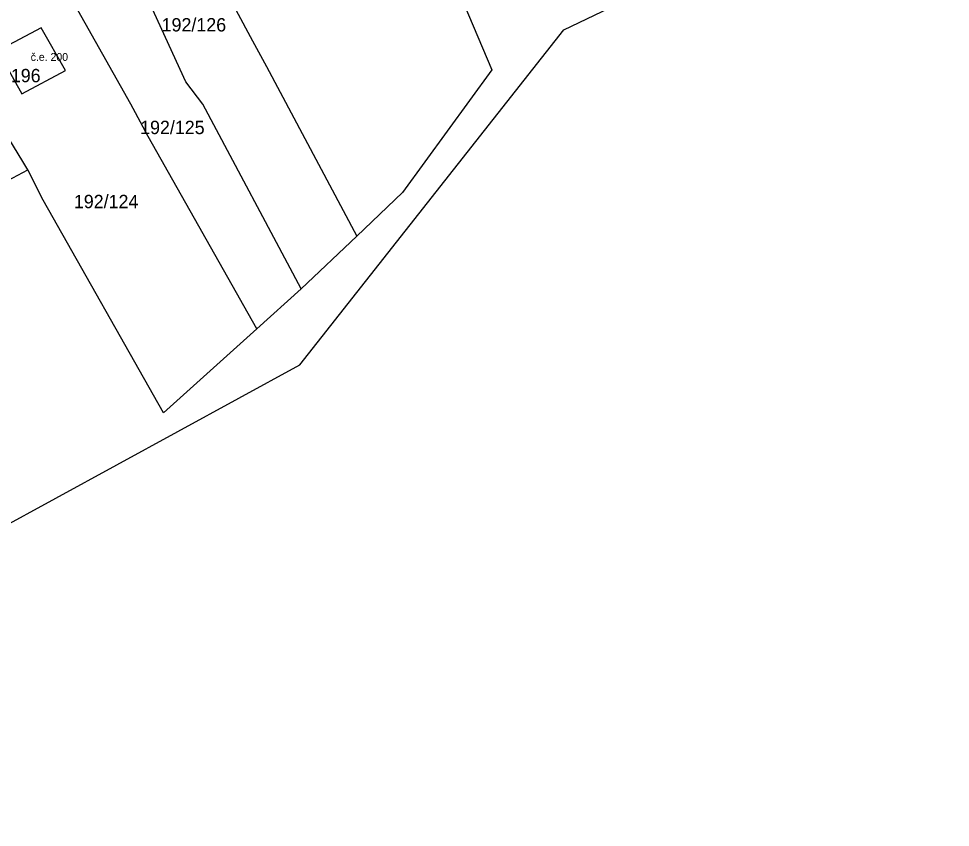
# Model space of a CAD drawing. Extents: x -887272 to -877616, y -1026687 to -1019819.
# Drawn here: x -882201.9 to -882083.2, y -1024320.7 to -1024217.6 of the extents above; entities that cross this region are included whole.
import ezdxf

# ---------------------------------------------------------------- set-up
doc = ezdxf.new("R2010")
doc.units = 0
for name, color, linetype in [('Definiční body', 7, 'Continuous'), ('Hranice parcel', 7, 'Continuous'), ('Parcelní čísla', 7, 'Continuous'), ('Polygon budovy', 7, 'Continuous')]:
    doc.layers.add(name, color=color, linetype=linetype)

msp = doc.modelspace()

# ---------------------------------------------------------------- linework, layer by layer
at = {"layer": 'Hranice parcel'}
for p, q in [((-882180.56, -1024225.66), (-882185.83, -1024214.12)), ((-882214.06, -1024243.9), (-882200.68, -1024236.89)), ((-882158.78, -1024245.34), (-882165.85, -1024252.03)), ((-882165.85, -1024252.03), (-882171.52, -1024257.13))]:
    msp.add_line(p, q, dxfattribs=at)
for points in [[(-882425.59, -1024292.38), (-882421.44, -1024309.52), (-882387.34, -1024318.62), (-882335.2, -1024317.62), (-882324.6, -1024318.36), (-882301.38, -1024320.66), (-882228.26, -1024295.72), (-882166.04, -1024261.72), (-882132.4, -1024219.02), (-882083.16, -1024195.4)], [(-882183.3, -1024199.45), (-882172.08, -1024220.45), (-882170.3, -1024223.69), (-882158.78, -1024245.34)], [(-882171.52, -1024257.13), (-882185.35, -1024232.63), (-882186.97, -1024229.61), (-882187.58, -1024228.52), (-882201.44, -1024203.82)], [(-882145.75, -1024214.26), (-882141.56, -1024224.13), (-882152.95, -1024239.76), (-882158.78, -1024245.34)], [(-882200.68, -1024236.89), (-882201.33, -1024235.82), (-882213.38, -1024216.04)], [(-882201.44, -1024227.17), (-882195.88, -1024224.22), (-882199, -1024218.76), (-882204.57, -1024221.7), (-882201.44, -1024227.17)], [(-882165.85, -1024252.03), (-882178.37, -1024228.51), (-882180.56, -1024225.66)], [(-882171.52, -1024257.13), (-882183.4, -1024267.82), (-882198.74, -1024240.75), (-882200.68, -1024236.89)]]:
    msp.add_lwpolyline(points, dxfattribs=at)
at = {"layer": 'Polygon budovy'}
msp.add_lwpolyline([(-882195.88, -1024224.22), (-882199, -1024218.76), (-882204.57, -1024221.7), (-882201.44, -1024227.17)], close=True, dxfattribs=at)

# ---------------------------------------------------------------- texts
at = {"layer": 'Definiční body'}
msp.add_text('č.e. 200', height=1, dxfattribs=at).set_placement((-882200.32, -1024222.99))
at = {"layer": 'Parcelní čísla'}
for s, p in [('192/126', (-882183.64, -1024219.24)), ('196', (-882202.85, -1024225.71)), ('192/125', (-882186.38, -1024232.32)), ('192/124', (-882194.82, -1024241.76))]:
    msp.add_text(s, height=1.7, dxfattribs=at).set_placement(p)

doc.saveas('drawing.dxf')
